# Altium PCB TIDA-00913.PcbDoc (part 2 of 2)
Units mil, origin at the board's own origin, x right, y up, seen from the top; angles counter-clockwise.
Board outline 3117.8 x 2115.91 mil, 4 copper layers (Top Layer, Internal Layer 1, Internal Layer 2, Bottom Layer), stack 61.6 mil thick; 181 components, 89 nets, 500 pads, 191 vias.
Unrouted connection lines stored in the file: 2.
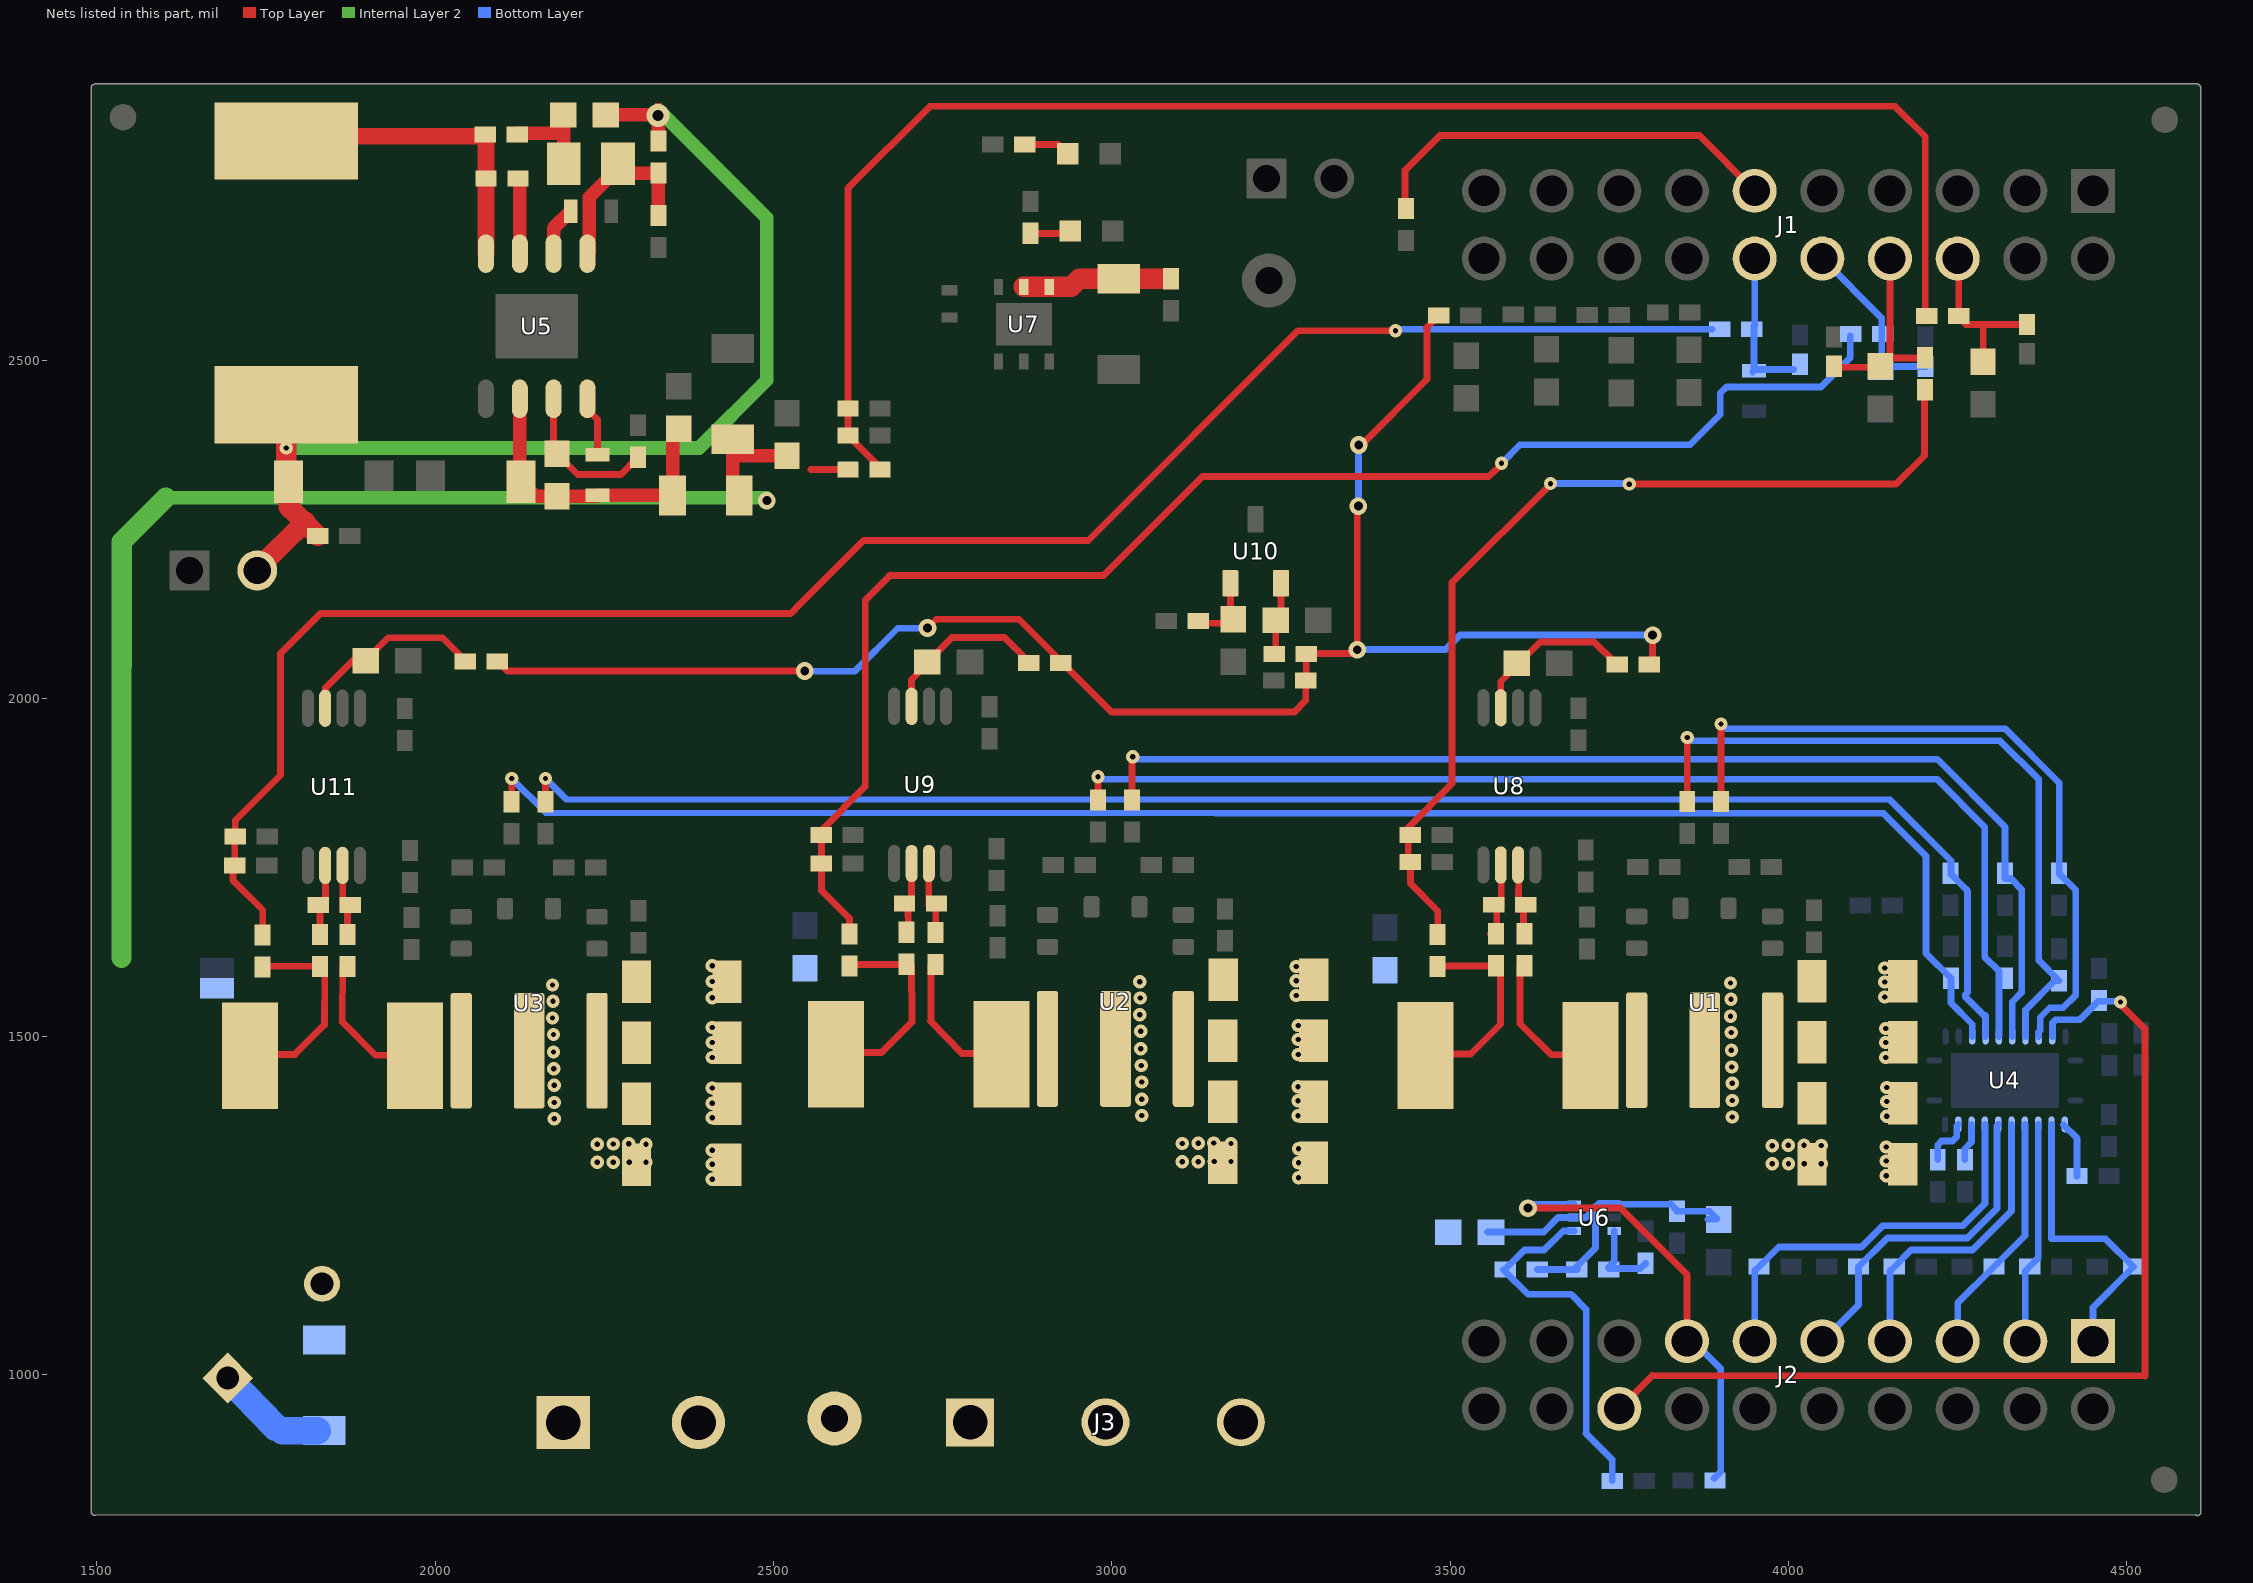
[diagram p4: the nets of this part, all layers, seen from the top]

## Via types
v1: diameter 19.68, hole 7.87, Top Layer to Bottom Layer, 168 vias
v2: diameter 25.98, hole 12.99, Top Layer to Bottom Layer, tented top, 22 vias
v3: diameter 34, hole 16, Top Layer to Bottom Layer, 1 vias

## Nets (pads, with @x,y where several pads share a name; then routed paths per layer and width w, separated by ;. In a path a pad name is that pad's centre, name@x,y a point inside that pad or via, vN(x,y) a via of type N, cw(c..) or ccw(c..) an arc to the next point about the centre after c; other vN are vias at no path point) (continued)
NetC33_1: C33.1 D4.2 J1.12 R15.2 | length 250.4
  Bottom Layer w10: J1.12@3934.21,2628.05 J1.12@3950,2643.84 ; C33.1@3947.21,2482.37 3947.21,2482.49 C33.1@3947.68,2482.96 ; C33.1@3947.68,2482.86 C33.1@3947.68,2482.96 ; C33.1@3948.97,2484.25 C33.1@3947.68,2482.96 ; J1.12@3950,2650 J1.12@3950,2643.84 ; J1.12@3952.16,2646 J1.12@3950,2643.84 ; D4.2@4007.34,2486.18 3949.21,2486.18 3949.21,2550.27 3950,2551.05 J1.12@3950,2643.84
NetC34_1: C34.1 D2.2 J1.10 R14.2 | length 259.6
  Bottom Layer w10: J1.10@4050,2650 4137.74,2562.26 4137.74,2492.79 4140.14,2490.38 D2.2@4202.76,2490.38
NetC35_1: C35.1 D3.2 J1.8 R13.2 | length 281.9
  Top Layer w10: D3.2@4069.12,2489.2 4131.63,2489.2 C35.1@4134.51,2492.09 ; C35.1@4135.56,2491.04 C35.1@4147.68,2503.16 ; J1.8@4150.05,2646.46 4150.05,2505.53 C35.1@4147.68,2503.16 ; R13.2@4201.6,2503.16 C35.1@4147.68,2503.16
NetC36_1: C36.1 D1.2 J1.6 R12.2 | length 238.6
  Top Layer w10: J1.6@4248.1,2642.2 4251.71,2638.59 R12.2@4251.71,2564.94 ; R12.2@4252.88,2561.79 4262.28,2552.38 4287.91,2552.38 ; C36.1@4289.5,2496.5 4287.91,2498.09 4287.91,2552.38 ; D1.2@4352.29,2552.38 4287.91,2552.38
NetC37_1: C37.1 U5.7 | length 114.2
  Top Layer w10: C37.1@2121.7,2770.13 C37.1@2125,2766.83
  Top Layer w20: U5.7@2125,2657.28 C37.1@2125,2766.83
NetC37_2: C37.2 L1.1 R40.1 U5.8 | length 398.3
  Top Layer w25: L1.1@1848.19,2830.69 R40.1@2076.05,2831.26 ; U5.8@2075,2657.28 R40.1@2075.11,2827.77
NetC38_1: C38.1 C40.1 C41.1 J5.2 L1.2 R41.2 | length 1670.4
  Top Layer w20: L1.2@1780,2445.12 L1.2@1783.07,2442.05 ; C38.1@2250.93,2862.32 v3@2329.44,2862.32 ; R41.2@2330,2823.62 v3@2330,2870
  Top Layer w30: J5.2@1736.68,2190.68 1808.2,2261.14 ; C40.1@1780,2320 v1(1780,2370) L1.2@1780,2445.12 ; C40.1@1783.07,2320 1783.07,2283.31 1793.72,2272.65 C41.1@1826.38,2240
  Internal Layer 2 w20: v1(1780,2370) 2390,2370 2490,2470 2490,2710 v3@2330,2870
  other v3: 2329.44,2861.51
NetC38_2: C38.2 C39.1 R40.2 | length 143.3
  Top Layer w20: R40.2@2122.18,2834.97 2187.02,2835.45 ; C39.1@2190,2790 C38.2@2190,2868.5
NetC39_2: C39.2 R41.1 R44.2 U5.5 | length 253.3
  Top Layer w20: U5.5@2225,2657.28 2227.87,2660.16 2227.87,2740.65 C39.2@2270,2782.78 ; C39.2@2283.62,2776.38 R41.1@2330,2776.38 R44.2@2330,2713.62
NetC44_1: C44.1 C45.1 L2.2 R42.1 R43.1 U5.2 | length 443.5
  Top Layer w20: C45.1@2125,2321.93 U5.2@2125,2442.72 ; C45.1@2126.93,2320 2148.43,2298.5 R43.1@2180,2298.5 2238.5,2298.5 R42.1@2240,2300 L2.2@2350.79,2300 C44.1@2350.79,2389.29
NetC46_1: C46.1 U5.6 | length 73.1
  Top Layer w20: U5.6@2175,2657.28 2175,2695 C46.1@2200,2720
NetC47_2: C47.2 R51.1 R52.1 R53.2 R54.2 U6.2 U6.4 | length 542.8
  Bottom Layer w10: R53.2@3555.15,1211.34 3638.36,1211.34 3659.66,1232.64 U6.2@3683.39,1232.64 3700.95,1232.64 3719.29,1250.98 3719.29,1252.23 3718.91,1252.61 ; R51.1@3628.7,1156.08 R52.1@3687.3,1156.08 3687.62,1156.08 R52.1@3688.29,1156.75 ; R52.1@3684.96,1158.08 3714.25,1186.71 ; 3714.92,1188.04 3714.92,1249.27 ; 3720.24,1253.28 3742.44,1253.52 U6.4@3747.16,1253.58 ; U6.4@3742.45,1252.32 3826.19,1252.32 C47.2@3834.74,1243.77 ; C47.2@3835.34,1241.98 3883.13,1241.98 R54.2@3893.44,1231.67 ; R54.2@3880.7,1230.18 R54.2@3893.99,1230.18
NetC49_1: C49.1 R49.1 U7.4 U7.5 | length 217.2
  Top Layer w30: U7.5@2870,2608.19 U7.4@2907.4,2608.19 2939.92,2608.19 2951.73,2620 C49.1@3010,2620 R49.1@3082.33,2620
NetC52_1: C52.1 R57.1 U8.3 | length 104.8
  Top Layer w10: C52.1@3601.19,1688.06 U8.3@3601.24,1749.69 ; R57.1@3608.56,1650.32 C52.1@3608.56,1693.15 ; C52.1@3619.29,1694.69 C52.1@3619.57,1694.96
NetC52_2: C52.2 R58.1 U8.2 | length 110.2
  Top Layer w10: R58.1@3559.29,1651.85 R58.1@3562.97,1655.53 ; R58.1@3568.88,1651.27 C52.2@3568.88,1697.09 ; C52.2@3575.65,1690.52 U8.2@3575.65,1749.69
NetC53_2: C53.2 R60.2 U8.7 | length 246.6
  Top Layer w10: U8.7@3574.78,1986.11 3574.78,2024.99 3633.1,2083.31 3712.85,2083.31 3743.45,2052.71 R60.2@3743.45,2050.53
NetC56_1: C56.1 R63.1 U9.3 | length 104.8
  Top Layer w10: C56.1@2729.54,1694.28 U9.3@2729.59,1755.91 ; R63.1@2739.87,1654.27 C56.1@2739.87,1697.1 ; C56.1@2748.52,1696.77 C56.1@2748.8,1697.05
NetC56_2: C56.2 R64.1 U9.2 | length 98.6
  Top Layer w10: C56.2@2698.56,1695.66 R64.1@2699.04,1656.27 ; C56.2@2704,1696.74 U9.2@2704,1755.91
NetC58_2: C58.2 R68.2 U9.7 | length 252.9
  Top Layer w10: U9.7@2704,1988.19 2704,2027.48 C58.2@2727.39,2050.86 ; C58.2@2727.46,2053.82 2763.57,2089.93 2841.51,2089.93 R68.2@2877.91,2053.53
NetC61_2: C61.2 L3.1 U10.1 | length 94.4
  Top Layer w10: L3.1@3132.3,2110.92 C61.2@3172.51,2110.92 ; U10.1@3175.2,2170 3175.2,2121.05 C61.2@3178.92,2117.33
NetC62_2: C62.2 R75.1 U10.2 | length 108.7
  Top Layer w10: R75.1@3240.18,2065.4 3242.3,2067.52 C62.2@3242.3,2115.4 3250,2123.1 U10.2@3250,2170
NetC63_1: C63.1 R71.1 U11.3 | length 106.4
  Top Layer w10: C63.1@1863.4,1689.15 U11.3@1863.46,1750.78 ; R71.1@1870.5,1651.07 1870.5,1691.81 C63.1@1873.38,1694.7
NetC63_2: C63.2 R72.1 U11.2 | length 107.5
  Top Layer w10: C63.2@1827.1,1694.29 1829.67,1691.72 R72.1@1829.67,1651.07 ; R72.1@1828.23,1649.63 R72.1@1829.67,1651.07 ; R72.1@1829.67,1649.07 R72.1@1829.67,1651.07 ; C63.2@1837.87,1691.61 U11.2@1837.87,1750.78
NetC64_2: C64.2 R76.2 U11.7 | length 288.9
  Top Layer w10: U11.7@1837.43,1985.43 1837.43,2014.77 1879.38,2056.72 C64.2@1897.2,2056.72 ; C64.2@1897.2,2046.57 C64.2@1897.2,2055.62 C64.2@1897.2,2056.72 ; R76.2@2042.69,2057.82 2010.9,2089.6 1930.52,2089.6 1897.64,2056.72 C64.2@1897.2,2056.72
NetD5_2: D5.2 R39.1 | length 68.8
  Top Layer w10: R39.1@2871.47,2818.56 2921.1,2818.56 D5.2@2934.67,2804.99
NetD6_2: D6.2 R50.1 | length 60
  Top Layer w10: R50.1@2880,2687.17 2934.88,2687.17 D6.2@2938.5,2690.79
NetJ1_11: J1.11 R17.1 | length 627.7
  Top Layer w10: R17.1@3433.39,2724.42 3433.39,2780.35 3484.79,2831.75 3868.25,2831.75 J1.11@3950,2750
NetJ2_1: J2.1 R21.2 U4.3 | length 442.3
  Bottom Layer w10: U4.3@4388.74,1370.32 4388.74,1201.26 4468.74,1201.26 R21.2@4510,1160 4450,1100 J2.1@4450,1050
NetJ2_3: J2.3 R24.2 U4.4 | length 328.2
  Bottom Layer w10: J2.3@4350,1050 4350,1153.62 R24.2@4356.38,1160 4369.06,1172.68 U4.4@4369.06,1370.32
NetJ2_5: J2.5 R25.2 U4.5 | length 361.5
  Bottom Layer w10: J2.5@4250,1050 4250,1106.38 R25.2@4303.62,1160 4349.37,1205.75 U4.5@4349.37,1370.32
NetJ2_7: J2.7 R26.2 U4.6 | length 448.1
  Bottom Layer w10: J2.7@4150,1050 4150,1153.62 R26.2@4156.38,1160 4181.06,1184.68 4272.1,1184.68 4329.69,1242.27 U4.6@4329.69,1370.32
NetJ2_9: J2.9 R27.2 U4.7 | length 497.4
  Bottom Layer w10: J2.9@4050,1050 4103.62,1103.62 R27.2@4103.62,1160 4146.18,1202.56 4264.7,1202.56 4308.19,1246.05 4308.19,1368.5 U4.7@4310,1370.32
NetJ2_11: J2.11 R29.2 U4.8 | length 602.2
  Bottom Layer w10: J2.11@3950,1050 3950,1153.62 R29.2@3956.38,1160 3985.66,1189.28 4107.63,1189.28 4138.78,1220.43 4257.3,1220.43 4290.31,1253.45 U4.8@4290.31,1370.32
NetJ2_16: J2.16 R30.1 U4.22 | length 1500.5
  Top Layer w10: J2.16@3750,953.62 J2.16@3750,950 3798.94,998.94 3798.94,999.03 ; 3798.94,999.76 3798.94,999.03 ; v1@4488.17,1549.93 4527.08,1511.02 4527.09,998.13 ; 4524.59,999.38 3798.94,999.03
  Bottom Layer w10: U4.22@4389.72,1500.24 4390,1500.51 4390,1520.5 4394.42,1524.92 4430.33,1524.92 4457.64,1552.23 4486.92,1552.23 v1@4488.9,1550.26
  other v1: 4490.57,1551.26
NetR28_2: R28.2 U4.2 | length 84.2
  Bottom Layer w10: U4.2@4406.61,1369.78 4426.43,1349.97 R28.2@4426.43,1293.78
NetR37_2: R37.2 U4.9 | length 56.3
  Bottom Layer w10: R37.2@4260.59,1318.22 4260.59,1334.4 4270.63,1344.44 U4.9@4270.63,1370.32
NetR38_2: R38.2 U4.10 | length 74
  Bottom Layer w10: R38.2@4220.59,1318.22 4220.59,1339.96 4226.26,1345.63 4242.24,1345.63 4248.86,1352.25 4248.86,1368.23 U4.10@4250.94,1370.32
NetR42_2: R42.2 U5.4 | length 88.9
  Top Layer w10: U5.4@2225,2442.72 2225.44,2442.28 2225.44,2426.94 2240,2412.38 R42.2@2240,2360
NetR43_2: R43.2 R45.2 U5.3 | length 226.6
  Top Layer w10: U5.3@2175,2442.72 2175,2366.5 R43.2@2180,2361.5 2210.71,2330.79 2274.41,2330.79 R45.2@2300,2356.38
NetR46_1: R46.1 R51.2 U6.1 | length 543.1
  Bottom Layer w10: R51.2@3578.45,1155.42 3579.66,1154.24 3615.48,1119.27 3678.72,1119.27 3679.54,1118.44 ; R51.2@3579.78,1154.75 3609.74,1184.71 3638.93,1184.71 3667.17,1212.95 U6.1@3683.39,1212.95 ; 3679.96,1118.03 3701.04,1096.95 3701.04,913.79 ; 3700.86,913.97 3701.04,913.79 ; R46.1@3739.48,843.67 3739.48,875.34 3701.04,913.79
NetR47_1: R47.1 R52.2 U6.6 | length 114.5
  Bottom Layer w10: R52.2@3734.06,1159.05 3742.45,1167.44 U6.6@3742.45,1212.95 ; R52.2@3734.88,1157.23 3780.9,1157.23 R47.1@3788.75,1165.08
OT: J2.13 R48.1 U6.3 | length 688.5
  Top Layer w10: v2@3615.06,1246.8 3751.83,1246.8 3850,1148.63 J2.13@3850,1050
  Bottom Layer w10: v2@3615.73,1247.28 3620.77,1252.32 U6.3@3683.39,1252.32 ; J2.13@3838.87,1049.08 J2.13@3850.3,1049.08 ; J2.13@3850,1050 3859.2,1050 3900.04,1009.16 3900.04,857.58 R48.1@3889.79,847.33
  other v2: 3615.06,1246.62
PGND: C1.2 C2.2 C4.2 C5.2 C6.2 C7.2 C9.1 C10.2 C11.2 C12.2 C20.1 C21.2 C22.2 C23.2 J4.2 NT1.1 R1.1 R2.1 R53.1 TP2.1 U1.9 U2.9 U3.9
  other v1: 2409.31,1289.51 3275.9,1291.61 4144.61,1294.31 2409.31,1311.51 3275.9,1313.61 4144.61,1316.31 2409.31,1332.24 3275.9,1334.33 4144.61,1337.04 2176.03,1378.58 2409.31,1380.09 3916.89,1381.38 4145.09,1382.28 3044.01,1383.48 3275.11,1383.28 2409.31,1401.51 2176.03,1402.76 4145.09,1404.28 3275.11,1405.28 3916.89,1405.56 3044.01,1407.66 2409.31,1424.03 4145.09,1425.01 3275.11,1426 2176.03,1428.21 3916.89,1431.01 3044.01,1433.11 2175.4,1452.39 3916.26,1455.19 3043.38,1457.29 2409.31,1469.2 4143.66,1469.3 3275.5,1473.76 2174.8,1477.3 3915.66,1480.1 3042.78,1482.2 4143.66,1491.29 2409.31,1491.51 3275.5,1495.76 2174.76,1503.3 3915.62,1506.1 3042.74,1508.2 4143.66,1512.02 2409.31,1513.64 3275.5,1516.49 2173.49,1527.48 3914.35,1530.28 3041.47,1532.38 2174.12,1552.3 3914.98,1555.1 2409.31,1557.34 3042.1,1557.2 4142.22,1558.7 3272.51,1560.86 2173.49,1576.48 3914.35,1579.28 3041.47,1581.38 4142.22,1580.7 2409.31,1581.51 3272.51,1582.86 4142.22,1601.43 3272.51,1603.59 2409.31,1604.7
PH-A: R55.1 R57.2 U1.8 | length 218.2
  Top Layer w10: R57.2@3603.14,1605.16 3603.39,1519.87 ; 3603.63,1518.89 3649.49,1473.11 R55.1@3714.2,1473.11 ; U1.8@3773.31,1477.44 U1.8@3775.76,1479.88
PH-B: R61.1 R63.2 U2.8 | length 218.8
  Top Layer w10: 2732.04,1522.95 2778.72,1475.2 R61.1@2843.43,1475.2 ; 2732.58,1522.83 R63.2@2732.75,1606.64 ; U2.8@2902.54,1479.52 U2.8@2904.99,1481.97
PH-C: R69.1 R71.2 U3.8 | length 219.8
  Top Layer w10: 1862.33,1522.26 1912.14,1472.44 R69.1@1976.85,1472.44 ; 1862.81,1523.7 R71.2@1863.29,1604.88 ; U3.8@2035.96,1476.76 U3.8@2038.41,1479.21
PWM_AH: R5.2 R31.2 U4.21 | length 1072.6
  Top Layer w10: R5.2@3900.39,1847.64 v1(3900.39,1962.21)
  Bottom Layer w10: v1(3900.39,1962.21) v1@3905.24,1957.37 ; v1@3901.39,1955.16 4320.12,1955.16 4400,1875.28 4400,1741.06 4424.69,1716.37 4424.69,1561.54 4405.94,1542.8 4386.17,1542.8 4372.13,1528.75 4372.13,1508.98 4370.04,1506.89 U4.21@4370.04,1500.24
PWM_AL: R6.2 R32.2 U4.20 | length 1057.3
  Top Layer w10: R6.2@3850.39,1847.64 v1(3850.39,1942.21)
  Bottom Layer w10: v1(3850.39,1942.21) v1@3853.11,1939.49 ; v1@3851.5,1936.91 4312.72,1937.28 4370,1880 4370,1612.62 R32.2@4400,1582.62 4393.33,1582.62 4350.35,1539.65 U4.20@4350.35,1500.24
PWM_BH: R7.2 R33.2 U4.19 | length 1724.3
  Top Layer w10: R7.2@3029.62,1849.73 v1@3029.62,1912.39
  Bottom Layer w10: v1@3030.74,1910 4220,1910 4320,1810 4320,1733.62 4328.76,1733.62 4344.69,1717.7 4344.69,1565.3 4330.67,1551.28 U4.19@4330.67,1500.24
  other v1: 3030.97,1913.74
PWM_BL: R8.2 R34.2 U4.18 | length 1696.6
  Top Layer w10: R8.2@2979.62,1849.73 v1(2979.62,1884.29)
  Bottom Layer w10: v1@2975.69,1880.55 4219.45,1880.55 4290,1810 4290,1617.86 4310.98,1596.87 U4.18@4310.98,1500.24
PWM_CH: R10.2 R35.2 U4.17 | length 2449.4
  Top Layer w10: R10.2@2163.05,1846.97 v1(2163.05,1881.54)
  Bottom Layer w10: v1@2165.17,1881.54 v1(2163.05,1881.54) 2193.6,1850.98 4150,1850 4240,1760 4240,1740.17 4257.08,1723.08 4264.29,1715.88 4264.29,1714.53 4264.69,1714.13 4264.69,1565.3 4261.65,1562.27 4261.65,1558.5 4290.16,1530 4291.3,1531.14 U4.17@4291.3,1500.24
PWM_CL: R11.2 R36.2 U4.16 | length 2466.9
  Top Layer w10: R11.2@2113.05,1846.97 v1(2113.05,1881.54)
  Bottom Layer w10: v1(2113.05,1881.54) 2163.6,1830.98 4140.26,1830 4203.19,1767.07 4203.19,1623.19 R36.2@4240,1586.38 4240,1550 4271.61,1518.39 U4.16@4271.61,1500.24
VA: C51.1 R13.1 R56.1 R59.2 | length 1437.4
  Top Layer w10: R56.1@3481.49,1650.86 3481.49,1686.14 3441.22,1726.41 3441.22,1758.57 3438.18,1761.61 3438.18,1809.42 3502.76,1874.01 3502.76,2170.93 v1@3650.28,2318.45 ; v1(3764.89,2316.65) 4159.08,2316.65 4200.96,2358.53 R13.1@4200.96,2454.84
  Bottom Layer w10: v1(3648.29,2317.4) v1@3762.56,2317.4
VA-MOTOR: J3.3 R55.2 R56.2 R58.2 | length 296.2
  Top Layer w10: R55.2@3463.35,1472.21 3465.56,1474.42 3530.39,1474.42 3574.8,1518.64 ; R56.2@3479.99,1604.61 R58.2@3559.29,1604.61 ; R58.2@3574.3,1604.91 3574.55,1518.64
VB: C55.1 R14.1 R62.1 R65.2 | length 2195.3
  Top Layer w10: R62.1@2612.27,1651.8 2612.27,1674.68 2570.94,1716.02 2570.94,1804.87 2635.52,1869.46 2635.52,2144.67 2672.47,2181.61 ; 2671.61,2181.61 2672.47,2181.61 ; 2672.98,2182.13 2672.47,2181.61 ; v1@3577.76,2347.89 3576.44,2346.62 3556.98,2327.87 3134.04,2327.87 2987.78,2181.61 2672.47,2181.61
  Bottom Layer w10: v1(3575.84,2347.25) 3603.4,2374.81 3854.74,2374.81 3899.07,2419.14 3899.07,2450.93 3908.45,2460.31 ; 3908.26,2459.99 4047.93,2459.99 ; 4048.11,2460.31 4091.39,2503.59 R14.1@4091.39,2535.41
VB-MOTOR: J3.2 R61.2 R62.2 R64.2 | length 286.3
  Top Layer w10: R61.2@2592.57,1474.29 2594.78,1476.5 2659.62,1476.5 2704.62,1521.55 ; R62.2@2617.91,1606.69 R64.2@2688.52,1606.69 ; R64.2@2703.91,1606.64 2704.73,1522.58
VBUS: C1.1 C2.1 C4.1 C5.1 C6.1 C7.1 C9.2 C10.1 C11.1 C12.1 C20.2 C21.1 C22.1 C23.1 C42.1 C43.1 J4.1 L2.1 R66.2 U1.1 U2.1 U3.1 | length 1952
  Top Layer w10: 2555.07,2338.21 R66.2@2610.14,2338.21
  Top Layer w20: L2.1@2440,2309.21 C42.1@2440,2383.07 ; 2448.5,2358.5 C43.1@2520,2358.5
  Internal Layer 2 w10: v2(2490.19,2292.22) v2@2492.6,2289.81
  Internal Layer 2 w20: 1536.38,2048.63 1536.71,2048.97 ; 1601.74,2296.39 v2@2490,2296.39
  Internal Layer 2 w30: 1536.38,1616.76 1536.38,2048.63 ; 1536.71,2048.97 1536.71,2231.37 1601.74,2296.39
  Bottom Layer w40: C1.1@1693.6,995.49 1764.2,922.2 ; 1774.26,917.56 C2.1@1825.72,917.56
  other v1: 3976.22,1312.22 3999.94,1312.22 4023.46,1312.35 4048.28,1312.35 2239.52,1314.18 2263.24,1314.18 2286.76,1314.31 2311.58,1314.31 3104.18,1315.31 3127.9,1315.31 3151.42,1315.43 3176.24,1315.43 3976.02,1338.99 3999.74,1339.39 4048.28,1339.07 4022.83,1339.71 2239.31,1340.95 2263.04,1341.35 2311.58,1341.03 2286.12,1341.67 3103.98,1342.07 3127.7,1342.48 3176.24,1342.16 3150.79,1342.8
VC: C60.1 R15.1 R70.1 R74.2 | length 2779.5
  Top Layer w10: R74.2@1701.18,1756.36 1701.18,1730.85 1745.12,1686.91 R70.1@1745.12,1650.29 ; C60.1@1703.35,1798.45 1703.78,1798.01 R74.2@1703.78,1752.81 ; C60.1@1704.49,1796.04 1704.49,1819.49 1771.36,1886.36 1771.36,2066.16 1830.55,2125.35 2525.63,2125.35 2532.63,2132.35 ; 2532.49,2132.49 2633.19,2233.19 2965.12,2233.19 3275.36,2543.44 v1(3419.24,2543.44)
  Bottom Layer w10: v1@3421.45,2545.34 R15.1@3887.41,2545.34
VC-MOTOR: J3.1 R69.2 R70.2 R72.2 | length 274.3
  Top Layer w10: R69.2@1728.21,1473.75 1793.05,1473.75 ; R70.2@1748.01,1603.94 R72.2@1821.94,1603.94 ; 1792.2,1473.75 1836.39,1517.94 ; 1836.39,1516.98 R72.2@1836.87,1589.99
VDC: C57.1 R12.1 R66.1 R67.2 | length 2356.4
  Top Layer w10: R66.1@2657.38,2340.96 R67.2@2610.14,2388.21 C57.1@2610.14,2428.21 2610.14,2753.97 2731.16,2875 4157.67,2875 4201.96,2830.7 R12.1@4201.96,2567.21
VREF: R20.1 R60.1 R68.1 R73.1 R75.2 R76.1 | length 2476.5
  Top Layer w10: R76.1@2089.84,2057.66 2107.05,2040.45 v2(2546.16,2040.45) ; v2(2727.6,2104.03) 2740.52,2116.94 2862.65,2116.94 2999.59,1980 3270,1980 3286.51,1996.51 R73.1@3286.51,2026.42 3287.42,2027.33 R75.2@3287.42,2065.4 ; R75.2@3285.02,2066.33 3356.99,2066.33 v2(3362.63,2071.96) v2@3362.63,2282.26 ; v2@3368.73,2374.4 3465.94,2471.61 3465.94,2548.48 ; 3464.69,2547.5 R20.1@3483.27,2566.08 ; R60.1@3794.01,2049.79 3799.21,2054.99 v2(3799.21,2093.56)
  Bottom Layer w10: v2@2549.07,2039.87 2549.21,2040 2620,2040 2683.64,2103.64 v2@2728.6,2103.64 ; v2(3364.38,2284.11) v2@3364.38,2374.4 ; v2@3365.1,2072.26 3493.25,2072.21 3514.59,2093.56 v2(3799.21,2093.56)
  other v2: 3364.86,2374.4
pads on no net: FID1.1 FID2.1 FID3.1 J1.3 J1.5 J1.7 J1.9 J1.13 J1.15 J1.17 J1.19 J2.4 J2.6 J2.8 J2.10 J2.12 J2.14 J2.15 J2.17 J2.18 J2.19 J2.20 U1.1A U1.1B U1.1C U1.1D U1.1E U1.8A U1.8B U1.8C U1.8D U1.8E U1.9A U1.9B U1.9C U1.9D U1.9E U2.1A U2.1B U2.1C U2.1D U2.1E U2.8A U2.8B U2.8C U2.8D U2.8E U2.9A U2.9B U2.9C U2.9D U2.9E U3.1A U3.1B U3.1C U3.1D U3.1E U3.8A U3.8B U3.8C U3.8D U3.8E U3.9A U3.9B U3.9C U3.9D U3.9E U4.14 U4.15 U4.25
copper on no net: | length 1.6
  Bottom Layer w10: 4042,2539.51 4043.13,2540.64
  other v1: 4319.19,1410.62 4381.99,1434.25 4245.04,1435.28 4319.02,1460.76

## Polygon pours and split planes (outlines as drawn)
PGND on Internal Layer 1 "PGND" (solid, remove dead copper, pour order 80): 3835.9,1285.48 4155.9,1285.48 4155.9,1613.68 3835.9,1613.68
PGND on Internal Layer 1 "PGND" (solid, remove dead copper, pour order 82): 2967.42,1285.48 3287.42,1285.48 3287.42,1613.15 2967.42,1613.15
PGND on Internal Layer 1 "PGND" (solid, remove dead copper, pour order 84): 2098.44,1282.91 2418.44,1282.91 2418.44,1613.68 2098.44,1613.68
GND on Internal Layer 1 "GND" (solid, remove dead copper, pour order 0): 3744.52,800 4600,800 4600,2900 1509.83,2900 1509.83,1646.62 4199.03,1646.62 4199.03,1254.51 4162.33,1217.81 3999.95,1217.81 3819.64,1217.81 3784.51,1182.68 3784.51,1128.73 3744.52,1100
PGND on Top Layer "PGND" (solid, pour order 100): 4181.85,1280.42 4181.85,1615.19 4130.53,1615.19 4130.53,1280.42 4156.57,1280.42
PGND on Top Layer "PGND" (solid, pour order 98): 2447.16,1283.6 2447.16,1618.37 2395.84,1618.37 2395.84,1283.6 2421.88,1283.6
PGND on Top Layer "PGND" (solid, pour order 94): 3314.51,1281.69 3314.51,1616.46 3263.18,1616.46 3263.18,1281.69 3289.22,1281.69
GND on Top Layer "TOP_LAYER_GND_P078" (solid, remove dead copper, pour order 78): 1863.76,2729.65 1863.76,2228.54 2549.68,2228.54 2560.79,2228.54 2560.79,2239.65 2560.79,2729.65
VBUS on Top Layer "TOP_LAYER_VBUS_P076" (solid, remove dead copper, pour order 76): 2402.62,2381.12 2402.62,2296.04 2428.66,2270 2530,2270 2570,2310 2570,2360 2550,2380 2548.88,2381.12
VA-MOTOR on Top Layer "TOP_LAYER_VA-MOTOR_P026" (solid, remove dead copper, pour order 26): 3325.12,1008.84 3451.36,1135.08 3505.48,1198.83 3505.48,1319.16 3505.48,1555.12 3364.29,1555.12 3364.29,1319.16 3341.77,1244.68 3247.87,1150.78 3170.2,1067.58 3129.63,943.31 3129.63,848.04 3271.12,848.04
VB-MOTOR on Top Layer "TOP_LAYER_VB-MOTOR_P060" (solid, remove dead copper, pour order 60): 3027.78,1164.55 2912.1,1265.81 2636.84,1392.67 2636.84,1555.49 2486.24,1555.49 2486.24,1339.39 2636.84,1253.12 2787.24,1175.19 2895.62,1111.05 2930.05,1032.39 2930.05,848.44 3063.07,848.44 3063.07,1067.91
VC-MOTOR on Top Layer "TOP_LAYER_VC-MOTOR_P058" (solid, pour order 58): 2104,1141.49 1816.03,1223.95 1637.45,1314.51 1637.45,1550.91 1771.04,1550.91 1771.04,1386.71 2045.65,1294.99 2478.24,1199.84 2751.27,1111.32 2867.7,994.88 2867.7,847 2702.78,847 2702.78,975.3 2433.84,1070.44
PH-A on Top Layer "PHA" (solid, pour order 24): 3792.15,1393.11 3792.15,1563.11 3672.15,1563.11 3672.15,1393.11
PGND on Top Layer "PGND" (solid, pour order 20): 3932.15,1374.43 3932.15,1593.11 3862.15,1593.11 3862.15,1374.43
VBUS on Top Layer "VBUS" (solid, pour order 4): 4062.15,1280.11 4062.15,1613.11 3962.15,1613.11 3962.15,1280.11
VBUS on Top Layer "VBUS" (solid, pour order 62): 3191.38,1284.2 3191.38,1615.2 3091.38,1615.2 3091.38,1284.2
PGND on Top Layer "PGND" (solid, pour order 64): 3061.38,1375.83 3061.38,1595.2 2991.38,1595.2 2991.38,1375.83
PH-B on Top Layer "PHA" (solid, pour order 66): 2921.38,1395.2 2921.38,1565.2 2801.38,1565.2 2801.38,1395.2
VBUS on Top Layer "VBUS" (solid, pour order 68): 2324.8,1281.44 2324.8,1612.44 2224.8,1612.44 2224.8,1281.44
PGND on Top Layer "PGND" (solid, pour order 70): 2194.8,1370.93 2194.8,1592.44 2124.8,1592.44 2124.8,1370.93
PH-C on Top Layer "PHA" (solid, pour order 72): 2054.8,1392.44 2054.8,1562.44 1934.8,1562.44 1934.8,1392.44
3V3 on Top Layer "3V3_top_pad" (solid, pour order 74): 3094.13,2591.01 3098.21,2591.01 3104.95,2584.27 3104.95,2501.54 3097.4,2493.98 3078.4,2494.19 3075.95,2494.19 3066.55,2503.59 3066.55,2585.49 3072.07,2591.01 3074.52,2591.01
NetC38_1 on Top Layer "NetC28-1" (solid, pour order 88): 1764.06,2155.72 1792.21,2155.72 1832.14,2195.65 1832.14,2408.08 1812.69,2427.54 1742.05,2427.54 1706.73,2392.22 1706.73,2172.61 1723.62,2155.72
3V3 on Internal Layer 2 "3V3" (solid, pour order 18): 3712.51,800 4600,800 4600,2900 1683.95,2900 1683.95,1814.32 4198.45,1814.32 4198.45,1252.51 4164.17,1218.24 3927.99,1218.24 3818.66,1218.24 3792.35,1177.47 3792.35,1141.4 3792.35,1096.57 3712.51,1024.89
VBUS on Internal Layer 2 "VBUS" (solid, remove dead copper, pour order 10): 1516,800 3434.14,800 3434.14,1133.77 3588.94,1272.79 4121.72,1272.79 4160,1290.13 4160,1613.54 1516,1613.54
5V on Internal Layer 2 "5V_plane_GAN" (solid, pour order 28): 4123.9,1749.67 1540.22,1749.67 1540.22,1682.07 1576.41,1645.88 4123.9,1645.88 4123.9,1715.24
PGND on Bottom Layer "PGND" (solid, remove dead copper, pour order 32): 1516,800 3434.14,800 3434.14,1131.3 3571.79,1257.41 3758.72,1257.41 4104.35,1264.73 4160,1289.14 4160,1613.54 1516,1613.54
GND on Bottom Layer "BOTTOM_LAYER_GND_P030" (solid, remove dead copper, pour order 30): 3744.52,800 4600,800 4600,2900 1516,2900 1516,1646.46 4197.28,1646.46 4197.28,1261.04 4161.35,1216.84 3819.64,1216.84 3744.52,1100 3744.52,864.52

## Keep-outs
Keep-Out Layer:
  text ".Layer_Name" at 577,-858.49 h60

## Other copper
Top Layer:
  pour cut-out: 2380,2270 2080,2270 2080,2220 2390,2220
  pour cut-out: 2060,2610 2001.3,2610 1911.3,2520 1860,2520 1860,2680 1860,2740 2050,2740
  text ".Layer_Name" at 577,-858.49 h60
Internal Layer 1:
  pour cut-out: 2026.62,2897.88 2026.62,2498.61 2081.94,2443.29 2081.94,2412.25 2081.94,2383.45 1512.19,2383.45 1512.19,2897.88
Internal Layer 2:
  pour cut-out: 2025.12,2899.39 2025.12,2500.11 2080.44,2444.79 2080.44,2413.75 2080.44,2313.59 1510.69,2313.59 1510.69,2899.39
  pour cut-out: 1605.89,2272.42 1590.28,2256.81 1590.28,2235.77 1597.82,2228.23 1670.01,2228.23 1677.81,2220.43 1754.92,2220.43 1768.79,2206.57 1773.12,2206.57 1773.12,2161.51 1786.12,2148.52 1787.85,2150.25 1840.71,2150.25 1948.15,2257.69 1948.15,2265.49 1939.48,2274.16
Bottom Layer:
  pour cut-out: 2025.12,2900.89 2025.12,2501.61 2080.44,2446.29 2080.44,2415.25 2080.44,2386.45 1510.69,2386.45 1510.69,2900.89
  text ".Layer_Name" at 577,-858.49 h60

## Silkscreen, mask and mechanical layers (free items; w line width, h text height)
Top Overlay:
  region: 4314.11,1881.34 4314.11,2181.34 4214.11,2181.34 4214.11,1881.34
  text "5V" at 3055.26,2788.33 h60
  text "3V3" at 3055.26,2672.74 h60
  text "VC   VB   VA" at 2690.96,1136.54 h100
  text "+48V   GND" at 2057.84,1132.44 h100
  text ".Layer_Name" at 577,-858.49 h60
Bottom Overlay:
  text ".Layer_Name" at 577,-858.49 h60
Top Paste:
  text ".Layer_Name" at 577,-858.49 h60
Bottom Paste:
  text ".Layer_Name" at 577,-858.49 h60
Top Solder:
  text ".Layer_Name" at 577,-858.49 h60
  text ".Layer_Name" at 577,-858.49 h60
Bottom Solder:
  text ".Layer_Name" at 577,-858.49 h60
Drill Guide:
  text ".Layer_Name" at 577,-858.49 h60
M1 Board Outline:
  lines w10: 1496.61,2902.43 1496.73,797.7 ; 1497.02,797.8 4603.46,798.54 ; 1498.44,2903.11 4603.58,2903.11 4603.58,2902.14 4604.38,2902.14 4604.38,797.21
  text ".Layer_Name" at 577,-858.49 h60
M2 Board Dimensions:
  rectangle: 0,-275 125,-150
  rectangle: 125,-400 500,-275
  lines w7: 0,-275 1000,-275 ; 125,-400 125,-150 ; 250,-400 250,-150 ; 500,-400 500,-150 ; 750,-400 750,-150 ; 0,-400 1000,-400 1000,-150 0,-150 0,-400
  text ".Layer_Name" at 577,-858.49 h60
M3 3D STEP Top:
  text ".Layer_Name" at 577,-858.49 h60
M4 3D STEP Bottom:
  text ".Layer_Name" at 577,-858.49 h60
M5 Assembly Top:
  lines w10: -292,-930.17 6308,-930.17 ; -292,-726.83 6310,-726.83 ; -292,-523.5 -292,-1133.5 3713,-1133.5 6310,-1133.5 6310,-523.5 -291.5,-523.5 -291.5,-1133.5 1284,-1133.5 ; 2173,-1133.5 2173,-523.5 ; 3440,-726.83 3440,-523.5 ; 4280,-726.83 4280,-523.5 ; 4902,-1140 4902,-937.17
  text "COMPONENTS MARKED 'DNP' SHOULD NOT BE POPULATED." at 1153.5,-318.5 h60
  text "ASSEMBLY VARIANT:" at 1153,-434 h60
  text ".VariantName" at 2189,-434 h60
  text "PCB VIEWED FROM TOP SIDE" at -228.5,-655.67 h60
  text "BOARD #:" at 2248,-655.67 h60
  text ".PRJ_Number" at 2793.5,-655.67 h60
  text "REV:" at 3638,-655.67 h60
  text ".PCB_Rev" at 3929.5,-655.67 h60
  text "SVN REV:" at 4476,-655.67 h60
  text ".VersionControl_RevNumber" at 4982,-655.67 h60
  text "TID #:" at 2248,-859 h60
  text ".TID" at 2793.5,-859 h60
  text "PLOT NAME =" at -228.5,-1064.34 h60
  text ".plot_File_Name" at 577,-1064.34 h60
  text "GENERATED    :" at 2250,-1064.34 h60
  text ".Print_Date" at 3119.5,-1064.34 h60
  text ".Print_Time" at 3848.5,-1064.34 h60
  text "TEXAS INSTRUMENTS" at 5113,-1064.34 h60
M6 Assembly Bottom:
  lines w10: -292.5,-727.33 6309.5,-727.33 ; -290.5,-930.67 6309.5,-930.67 ; 1115.5,-1140.5 1115.5,-937.67 ; 1737.5,-727.33 1737.5,-524 ; 2577.5,-727.33 2577.5,-524 ; 3844.5,-1134 3844.5,-524 ; 4733.5,-1134 6309,-1134 6309,-524 -292.5,-524 -292.5,-1134 2304.5,-1134 6309.5,-1134 6309.5,-524
  text "COMPONENTS MARKED 'DNP' SHOULD NOT BE POPULATED." at 6102,-318 h60
  text ".VariantName" at 5058,-434 h60
  text "ASSEMBLY VARIANT:" at 6097,-434 h60
  text ".VersionControl_RevNumber" at 1035.5,-656.17 h60
  text "SVN REV:" at 1541.5,-656.17 h60
  text ".PCB_Rev" at 2088,-656.17 h60
  text "REV:" at 2379.5,-656.17 h60
  text ".PRJ_Number" at 3224,-656.17 h60
  text "BOARD #:" at 3769.5,-656.17 h60
  text "PCB VIEWED FROM BOTTOM SIDE" at 6246,-656.17 h60
  text ".TID" at 3224,-859.5 h60
  text "TID #:" at 3769.5,-859.5 h60
  text "TEXAS INSTRUMENTS" at 904.5,-1064.84 h60
  text ".Print_Time" at 2169,-1064.84 h60
  text ".Print_Date" at 2898,-1064.84 h60
  text "GENERATED    :" at 3767.5,-1064.84 h60
  text ".plot_File_Name" at 5440.5,-1064.84 h60
  text "PLOT NAME =" at 6246,-1064.84 h60
M9 Title Sheet:
  drawing of 57 lines, arcs and shapes, not listed
  text "1" at 739.84,8036.5 h70
  text "2" at 3235.5,8036.5 h70
  text "3" at 5724.84,8036.5 h70
  text "4" at 8231.51,8036.5 h70
  text "5" at 10730.5,8036.5 h70
  text "6" at 13235.5,8036.5 h70
  text "A" at -416.5,6893.5 h70
  text "A" at 14383.5,6893.5 h70
  text "B" at -416.5,4513.5 h70
  text "B" at 14383.5,4513.5 h70
  text "C" at -416.5,2138.5 h70
  text "C" at 14383.5,2138.5 h70
  text "PROJECT TITLE:" at 11343.5,277.5 h45
  text ".PRJ_Title" at 11393.5,144.17 h70
  text "DESIGNED FOR:" at 11343.5,-23.5 h45
  text ".PRJ_Customer" at 11393.5,-163.5 h70
  text "D" at -416.5,-231.5 h70
  text "D" at 14383.5,-231.5 h70
  text "FILE NAME:" at 11343.5,-323.5 h45
  text ".PCB_File_Name_No_Path" at 11393.5,-443.5 h70
  text "Texas Instruments (TI) and/or its licensors do not warrant the accuracy or completeness of this specification" at 6374,-605.34 h45
  text "ENGINEER:" at 11343.5,-613.5 h45
  text "LAYOUT BY:" at 12848.5,-613.5 h45
  text "or any information contained therein. TI and/or its licensors do not warrant that this design will meet" at 6329.01,-718 h45
  text ".PRJ_Engineer" at 11393.5,-768.49 h70
  text ".PCB_Layout" at 12899,-768.49 h70
  text "the specifications, will be suitable for your application or fit for any particular purpose, or will operate in" at 6329.01,-830.67 h45
  text ".Layer_Name" at 577,-858.49 h60
  text "ALTIUM DESIGNER VERSION:" at 12848.5,-923.5 h45
  text "an implementation. TI and/or its licensors do not warrant that the design is production worthy. You should" at 6329.01,-943.33 h45
  text "completely validate and test your design implementation to confirm the system functionality for your application." at 6374,-1056 h45
  text ".print_Scale" at 11393.5,-1056.83 h70
  text ".Application_BuildNumber" at 12899,-1056.83 h70
  text "1" at 739.84,-1263.5 h70
  text "2" at 3235.5,-1263.5 h70
  text "3" at 5724.84,-1263.5 h70
  text "4" at 8231.51,-1263.5 h70
  text "5" at 10730.5,-1263.5 h70
  text "6" at 13235.5,-1263.5 h70
M10 Fab Notes:
  drawing of 173 lines, arcs and shapes, not listed
  text "DESIGN INFORMATION" at 12378.02,6201 h60
  text "MIN. TRACK WIDTH:" at 11733.46,6021 h60
  text "8" at 12829.7,6021 h60
  text "MIL" at 12984.46,6021 h60
  text "MIN. CLEARANCE:" at 11733.46,5889 h60
  text "0.2" at 12769.7,5889 h60
  text "mm" at 12984.46,5889 h60
  text "MIN. VIA PAD SIZE:" at 11733.46,5757 h60
  text "24" at 12799.71,5757 h60
  text "MIL" at 12984.46,5757 h60
  text "0.05mm (2MIL)" at 12428.46,5615.29 h60
  text "MINIMUM ANNULAR RING" at 11404.23,5611 h60
  text "EXTERNAL" at 13136.46,5611 h60
  text "PER" at 11604.23,5493 h60
  text "IPC-D-275 CLASS 2 LEVEL C" at 11824.23,5493 h60
  text "MIL, HOLES" at 13312.46,5380.71 h60
  text "+/-" at 12920,5380 h60
  text "+/-" at 13774,5380 h60
  text "REGISTRATION TOLERANCES:" at 11404.23,5375 h60
  text "METAL" at 12604,5375 h60
  text "5" at 13180.2,5375 h60
  text "3" at 14013.2,5375 h60
  text "MIL" at 14129.46,5375 h60
  text "+/-" at 13774,5262 h60
  text "HOLE SIZE TOLERANCE (UNLESS OTHERWISE SPECIFIED):" at 11404.23,5257 h60
  text "3" at 14013.2,5257 h60
  text "MIL" at 14129.46,5257 h60
  text "MATERIAL:" at 11329.46,5047.54 h60
  text "FR-4 High Tg" at 12315.9,4907.21 h60
  text "FR-408" at 11750.46,4898.64 h60
  text "OTHER" at 13238.46,4898.64 h60
  text "X" at 12161,4895 h60
  text "62 MIL (1.6mm) +/-10%" at 12070.56,4735.92 h60
  text "THICKNESS:" at 11404.23,4731.64 h60
  text "X" at 11942.4,4731.64 h60
  text "OTHER" at 13355.46,4731.64 h60
  text "TOLERANCE:" at 11404.23,4573.64 h60
  text "X" at 12243.53,4573.64 h60
  text "ANSI IPC-6012 TYPE 3 CLASS 2" at 12430.48,4573.64 h60
  text "OTHER +/-" at 12430.46,4417.64 h60
  text "BOW & TWIST:" at 11404.23,4260.64 h60
  text "X" at 12243.53,4260.64 h60
  text "ANSI IPC-6012 TYPE 3 CLASS 2" at 12430.48,4260.64 h60
  text "OTHER +/-" at 12430.46,4102.13 h60
  text "DRILLING:" at 11329.46,3963.64 h60
  text "REFERENCE:" at 11404.23,3846.64 h60
  text "X" at 12052.46,3846.64 h60
  text "AS SHOWN" at 12239.46,3846.64 h60
  text "X" at 12953.46,3846.64 h60
  text "NC_DRILL FILES" at 13090.46,3846.64 h60
  text "PTH COPPER THICKNESS:" at 11404.23,3688.64 h60
  text "X" at 12534.46,3688.64 h60
  text "20-30 um" at 12671.46,3688.64 h60
  text "OTHER" at 13388.46,3688.64 h60
  text "BOARD FINISH:" at 11329.46,3529.64 h60
  text "SILKSCREEN:" at 11484.68,3411.64 h60
  text "X" at 12433.46,3411.64 h60
  text "TOP" at 12559.46,3411.64 h60
  text "X" at 12943.46,3411.64 h60
  text "BOTTOM" at 13070.46,3411.64 h60
  text "SILKSCREEN COLOR:" at 11484.68,3244.64 h60
  text "X" at 12432.42,3244.64 h60
  text "WHITE" at 12559.46,3244.64 h60
  text "OTHER" at 13070.46,3244.64 h60
  text "X" at 12563.42,3085.44 h60
  text "GREEN" at 12690.46,3085.44 h60
  text "OTHER" at 13308.46,3085.44 h60
  text "SOLDER RESIST COLOR:" at 11484.68,3074.64 h60
  text "X" at 12563.42,2915.44 h60
  text "MATTE" at 12690.46,2915.44 h60
  text "SEMI-GLOSS" at 13308,2914.8 h60
  text "IMMERSION GOLD (ENIG)" at 12390.46,2726.92 h60
  text "ENEPIG" at 13728,2723.64 h60
  text "SURFACE FINISH:" at 11329.46,2722.64 h60
  text "X" at 12203.51,2722.64 h60
  text "IMM. TIN/SILVER OR EQUIV" at 11659,2565.64 h60
  text "OTHER" at 13090.46,2565.64 h60
  text "ARRAY/PANEL:" at 11329.46,2386.64 h60
  text "CUT AND TRIM PER M1 BOARD OUTLINE" at 12390.46,2382.35 h60
  text "N.C. ROUTE" at 12390.46,2230.64 h60
  text "X" at 13069.46,2230.64 h60
  text "V. SCORE" at 13256.46,2230.64 h60
  text "CERTIFICATION:" at 11329.46,2093.64 h60
  text "MATERIALS AND WORKMANSHIP FOR ALL PCBS" at 12054.46,2093.64 h60
  text "TO MEET OR EXCEED THE REQUIREMENTS OF:" at 12054.46,1995.64 h60
  text "X" at 11680.96,1859.13 h60
  text "ANSI IPC-A-600F CLASS ->" at 11819.96,1859.13 h60
  text "X" at 13459.02,1859.13 h60
  text "2" at 13577.96,1859.14 h60
  text "1" at 13262.96,1857.64 h60
  text "3" at 13931.96,1857.64 h60
  text "X" at 12495.02,1699.64 h60
  text "RoHS" at 12631.96,1699.64 h60
  text "OTHER" at 13276.36,1699.64 h60
  text "PER ORDER" at 13673.42,1699.64 h60
  text "ALL BOARDS MUST MEET OR EXCEED UL94-V0 REQUIREMENTS." at 11357,1534 h60
  text "PCB MUST BEAR THE UL94V-0 UL REGISTERED MATERIAL ID NUMBER" at 11357,1414 h60
  text "ADDITIONAL REQUIREMENTS:" at 11329.46,1240.64 h60
  text "MICROSECTION:" at 11404.23,1125.64 h60
  text "YES" at 12309.96,1125.64 h60
  text "REQUIRED" at 13171.46,969.49 h60
  text "BARE BOARD ELEC. TEST:" at 11404.23,966.64 h60
  text "NONE" at 12709.96,966.64 h60
  text "X" at 13044.46,966.64 h60
  text "PER ORDER" at 13763.46,966.64 h60
  text ".Layer_Name" at 577,-858.49 h60
M11 Gerber Information:
  lines w10: -292,-930.17 6308,-930.17 ; -292,-726.83 6310,-726.83 ; -292,-523.5 -292,-1133.5 3713,-1133.5 6310,-1133.5 6310,-523.5 -291.5,-523.5 -291.5,-1133.5 1284,-1133.5 ; 2173,-1133.5 2173,-523.5 ; 3440,-726.83 3440,-523.5 ; 4280,-726.83 4280,-523.5 ; 4902,-1140 4902,-937.17
  text "ALL ARTWORK VIEWED FROM TOP SIDE" at -228.5,-655.67 h60
  text "BOARD #:" at 2248,-655.67 h60
  text ".PRJ_Number" at 2793.5,-655.67 h60
  text "REV:" at 3638,-655.67 h60
  text ".PCB_Rev" at 3929.5,-655.67 h60
  text "SVN REV:" at 4476,-655.67 h60
  text ".VersionControl_RevNumber" at 4982,-655.67 h60
  text "LAYER NAME =" at -228.5,-858.49 h60
  text "TID #:" at 2248,-859 h60
  text ".TID" at 2793.5,-859 h60
  text "PLOT NAME =" at -228.5,-1064.34 h60
  text ".plot_File_Name" at 577,-1064.34 h60
  text "GENERATED    :" at 2250,-1064.34 h60
  text ".Print_Date" at 3119.5,-1064.34 h60
  text ".Print_Time" at 3848.5,-1064.34 h60
  text "TEXAS INSTRUMENTS" at 5113,-1064.34 h60
M12 Stackup:
  drawing of 295 lines, arcs and shapes, not listed
  text "Layer" at 9797.84,7830 h60
  text "Name" at 10207.76,7830 h60
  text "Material" at 11257.46,7830 h60
  text "Thickness" at 12117.23,7830 h60
  text "Constant" at 12767.06,7830 h60
  text "Board Layer Stack" at 13336.92,7830 h60
  text "1" at 9797.84,7710 h60
  text "Top Overlay" at 10207.76,7710 h60
  text "2" at 9797.84,7590 h60
  text "Top Solder" at 10207.76,7590 h60
  text "Solder Resist" at 11257.46,7590 h60
  text "0.40mil" at 12117.23,7590 h60
  text "3.5" at 12767.06,7590 h60
  text "3" at 9797.84,7470 h60
  text "Top Layer" at 10207.76,7470 h60
  text "Copper" at 11257.46,7470 h60
  text "1.40mil" at 12117.23,7470 h60
  text "4" at 9797.84,7350 h60
  text "Dielectric1" at 10207.76,7350 h60
  text "FR-4" at 11257.46,7350 h60
  text "10.00mil" at 12117.23,7350 h60
  text "4.2" at 12767.06,7350 h60
  text "5" at 9797.84,7230 h60
  text "Internal Layer 1" at 10207.76,7230 h60
  text "Copper" at 11257.46,7230 h60
  text "1.40mil" at 12117.23,7230 h60
  text "6" at 9797.84,7110 h60
  text "Dielectric 3" at 10207.76,7110 h60
  text "FR-4" at 11257.46,7110 h60
  text "36.00mil" at 12117.23,7110 h60
  text "4.2" at 12767.06,7110 h60
  text "7" at 9797.84,6990 h60
  text "Internal Layer 2" at 10207.76,6990 h60
  text "Copper" at 11257.46,6990 h60
  text "1.40mil" at 12117.23,6990 h60
  text "8" at 9797.84,6870 h60
  text "Dielectric 2" at 10207.76,6870 h60
  text "FR-4" at 11257.46,6870 h60
  text "10.00mil" at 12117.23,6870 h60
  text "4.2" at 12767.06,6870 h60
  text "9" at 9797.84,6750 h60
  text "Bottom Layer" at 10207.76,6750 h60
  text "Copper" at 11257.46,6750 h60
  text "1.40mil" at 12117.23,6750 h60
  text "10" at 9797.84,6630 h60
  text "Bottom Solder" at 10207.76,6630 h60
  text "Solder Resist" at 11257.46,6630 h60
  text "0.40mil" at 12117.23,6630 h60
  text "3.5" at 12767.06,6630 h60
  text "11" at 9797.84,6510 h60
  text "Bottom Overlay" at 10207.76,6510 h60
  text ".Layer_Name" at 577,-858.49 h60
M13 Component Bodies Top:
  text ".Layer_Name" at 577,-858.49 h60
M14 Component Bodies Bottom:
  text ".Layer_Name" at 577,-858.49 h60
M15 Courtyards Top:
  text ".Layer_Name" at 577,-858.49 h60
M16 Courtyards Bottom:
  text ".Layer_Name" at 577,-858.49 h60
Drill Drawing:
  circle w10: c5348.9,3003.91 r22.14
  lines w10: 5326.76,2727.18 5371.04,2727.18 5348.9,2682.91 5326.76,2727.18 ; 5326.76,2793.6 5337.83,2793.6 5337.83,2782.53 5359.97,2782.53 5359.97,2793.6 5371.04,2793.6 5371.04,2815.74 5359.97,2815.74 5359.97,2826.81 5337.83,2826.81 5337.83,2815.74 5326.76,2815.74 5326.76,2793.6 ; 5326.76,2882.15 5371.04,2882.15 5371.04,2926.43 5326.76,2926.43 5326.76,2882.15 ; 5326.76,3103.54 5348.9,3081.4 5371.04,3103.54 5348.9,3125.67 5326.76,3103.54 ; 5326.76,3192.09 5337.83,3192.09 5348.9,3181.02 5359.97,3192.09 5371.04,3192.09 5359.97,3203.16 5371.04,3214.23 5359.97,3214.23 5348.9,3225.3 5337.83,3214.23 5326.76,3214.23 5337.83,3203.16 5326.76,3192.09 ; 5326.76,3280.64 5348.9,3291.71 5371.04,3280.64 5359.97,3302.78 5371.04,3324.92 5348.9,3313.85 5326.76,3324.92 5337.83,3302.78 5326.76,3280.64
  lines w12: 5286,2653.02 8398.94,2653.02 ; 5286,3350.38 8398.94,3350.38 ; 5601.63,2553.4 5601.63,3450 ; 5918.82,2553.4 5918.82,3450 ; 6540.56,2553.4 6540.56,3450 ; 6784.88,2553.4 6784.88,3450 ; 7145.22,2553.4 7145.22,3450 ; 7854.73,2553.4 7854.73,3450 ; 5286,2553.4 8398.94,2553.4 8398.94,3450 5286,3450 5286,2553.4
  text "Symbol" at 5345.77,3380.26 h72
  text "Quantity" at 5631.52,3380.26 h72
  text "Finished Hole Size" at 5948.7,3380.26 h72
  text "Plated" at 6570.45,3380.26 h72
  text "Hole Type" at 6814.77,3380.26 h72
  text "Drill Layer Pair" at 7175.11,3380.26 h72
  text "Hole Tolerance" at 7884.62,3380.26 h72
  text "168" at 5631.52,3280.64 h60
  text "7.87mil (0.200mm)" at 5948.7,3280.64 h60
  text "PTH" at 6570.45,3280.64 h60
  text "Round" at 6814.77,3280.64 h60
  text "Top Layer - Bottom Layer" at 7175.11,3280.64 h60
  text "22" at 5631.52,3181.02 h60
  text "12.99mil (0.330mm)" at 5948.7,3181.02 h60
  text "PTH" at 6570.45,3181.02 h60
  text "Round" at 6814.77,3181.02 h60
  text "Top Layer - Bottom Layer" at 7175.11,3181.02 h60
  text "1" at 5631.52,3081.4 h60
  text "16.00mil (0.406mm)" at 5948.7,3081.4 h60
  text "PTH" at 6570.45,3081.4 h60
  text "Round" at 6814.77,3081.4 h60
  text "Top Layer - Bottom Layer" at 7175.11,3081.4 h60
  text "2" at 5631.52,2981.77 h60
  text "33.46mil (0.850mm)" at 5948.7,2981.77 h60
  text "PTH" at 6570.45,2981.77 h60
  text "Round" at 6814.77,2981.77 h60
  text "Top Layer - Bottom Layer" at 7175.11,2981.77 h60
  text "6" at 5631.52,2882.15 h60
  text "40.00mil (1.016mm)" at 5948.7,2882.15 h60
  text "PTH" at 6570.45,2882.15 h60
  text "Round" at 6814.77,2882.15 h60
  text "Top Layer - Bottom Layer" at 7175.11,2882.15 h60
  text "40" at 5631.52,2782.53 h60
  text "45.28mil (1.150mm)" at 5948.7,2782.53 h60
  text "PTH" at 6570.45,2782.53 h60
  text "Round" at 6814.77,2782.53 h60
  text "Top Layer - Bottom Layer" at 7175.11,2782.53 h60
  text "5" at 5631.52,2682.91 h60
  text "51.18mil (1.300mm)" at 5948.7,2682.91 h60
  text "PTH" at 6570.45,2682.91 h60
  text "Round" at 6814.77,2682.91 h60
  text "Top Layer - Bottom Layer" at 7175.11,2682.91 h60
  text "244 Total" at 5631.52,2583.29 h60
  text ".Layer_Name" at 577,-858.49 h60
M17 Embedded Cavity:
  text ".Layer_Name" at 577,-858.49 h60
M18 Embedded Assembly:
  text ".Layer_Name" at 577,-858.49 h60
M19 Embedded Keepout:
  text ".Layer_Name" at 577,-858.49 h60

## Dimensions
0,-400 to 1000,-400 on M2 Board Dimensions
1498.44,2903.11 to 1497.02,797.8 on M2 Board Dimensions
1496.73,797.7 to 4604.38,797.21 on M2 Board Dimensions
1496.73,797.7 to 4604.38,797.21 on M2 Board Dimensions
1498.44,2903.11 to 1497.02,797.8 on M2 Board Dimensions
